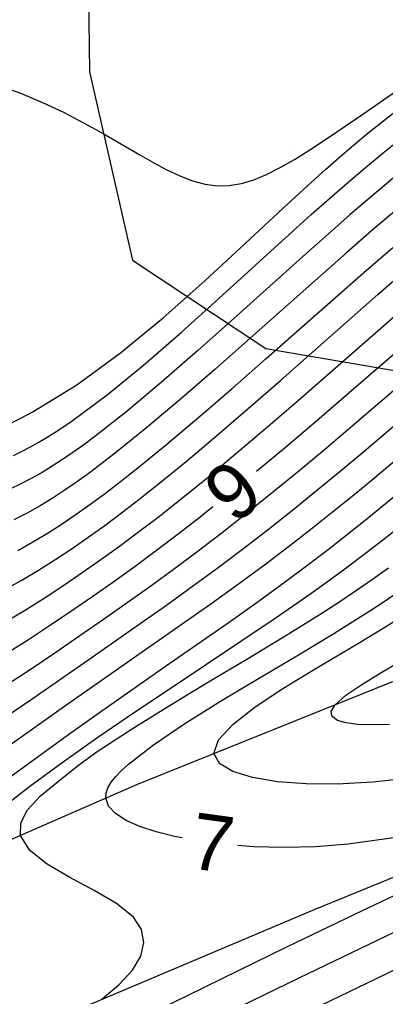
# Model space of a CAD drawing. Extents: x 2602990 to 2605851, y 618069 to 619180.
# Drawn here: x 2603320.28 to 2603333.31, y 618439.82 to 618474.55 of the extents above; entities that cross this region are included whole.
import ezdxf

# ---------------------------------------------------------------- set-up
doc = ezdxf.new("R2010")
doc.units = 0
for name, color, linetype in [('DTM Contours Major', 7, 'Continuous'), ('DTM Contours Minor', 7, 'Continuous'), ('DTM Contours Minor Text', 7, 'Continuous'), ('Exist DTM Crownline', 7, 'Continuous'), ('Exist DTM QL2 LIDAR Elevation Point', 7, 'Continuous'), ('Exist Roads EOP', 7, 'Continuous'), ('PH Exist DTM Breakline', 7, 'Continuous'), ('PH Exist DTM Obscure Area', 7, 'Continuous')]:
    doc.layers.add(name, color=color, linetype=linetype)

msp = doc.modelspace()

# ---------------------------------------------------------------- linework, layer by layer
at = {"layer": 'DTM Contours Major'}
for points in [[(2603319.853, 618472.09), (2603320.346, 618471.915), (2603321.104, 618471.603), (2603321.843, 618471.254), (2603322.561, 618470.88), (2603323.256, 618470.494), (2603324.568, 618469.736), (2603325.056, 618469.458), (2603325.528, 618469.205), (2603325.988, 618468.987), (2603326.438, 618468.813), (2603326.883, 618468.692), (2603327.324, 618468.635), (2603327.749, 618468.646), (2603328.179, 618468.72), (2603328.62, 618468.854), (2603329.078, 618469.044), (2603329.557, 618469.286), (2603330.063, 618469.576), (2603330.65, 618469.942), (2603331.282, 618470.358), (2603332.501, 618471.187), (2603333.853, 618472.117)], [(2603319.765, 618449.745), (2603320.729, 618450.401), (2603322.709, 618451.772), (2603324.576, 618453.074), (2603325.508, 618453.734), (2603326.437, 618454.4), (2603327.357, 618455.074), (2603328.267, 618455.756), (2603329.141, 618456.43), (2603330.003, 618457.112), (2603330.855, 618457.801), (2603331.697, 618458.494), (2603332.532, 618459.19), (2603334.227, 618460.626)]]:
    msp.add_lwpolyline(points, dxfattribs=at)
at = {"layer": 'DTM Contours Minor'}
for points in [[(2603319.929, 618460.176), (2603320.33, 618460.375), (2603320.728, 618460.586), (2603322.319, 618461.562), (2603323.877, 618462.7), (2603325.398, 618463.947), (2603326.874, 618465.255), (2603328.298, 618466.571), (2603329.663, 618467.846), (2603330.669, 618468.768), (2603331.167, 618469.213), (2603331.665, 618469.65), (2603332.167, 618470.08), (2603332.677, 618470.505), (2603333.864, 618471.449), (2603335.103, 618472.367), (2603336.387, 618473.248), (2603337.712, 618474.083), (2603339.073, 618474.862)], [(2603320.064, 618459.053), (2603320.38, 618459.208), (2603320.673, 618459.361), (2603320.965, 618459.524), (2603321.259, 618459.698), (2603321.554, 618459.882), (2603321.853, 618460.077), (2603322.157, 618460.284), (2603323.396, 618461.204), (2603324.696, 618462.264), (2603326.033, 618463.419), (2603327.38, 618464.627), (2603330.009, 618467.023), (2603330.668, 618467.616), (2603331.315, 618468.189), (2603331.954, 618468.745), (2603332.591, 618469.286), (2603333.231, 618469.814), (2603333.879, 618470.333)], [(2603333.578, 618468.906), (2603332.822, 618468.273), (2603332.056, 618467.615), (2603331.276, 618466.932), (2603330.477, 618466.223), (2603327.912, 618463.923), (2603326.613, 618462.768), (2603325.336, 618461.659), (2603324.11, 618460.632), (2603322.959, 618459.724), (2603322.566, 618459.432), (2603322.184, 618459.16), (2603321.811, 618458.906), (2603321.444, 618458.67), (2603321.081, 618458.45), (2603320.719, 618458.246), (2603320.329, 618458.044), (2603319.935, 618457.857)], [(2603333.71, 618467.798), (2603332.825, 618467.043), (2603331.919, 618466.254), (2603330.989, 618465.435), (2603328.488, 618463.217), (2603327.231, 618462.11), (2603325.999, 618461.043), (2603324.815, 618460.044), (2603323.701, 618459.142), (2603323.224, 618458.772), (2603322.763, 618458.426), (2603322.314, 618458.104), (2603321.875, 618457.803), (2603321.441, 618457.523), (2603321.011, 618457.262), (2603320.548, 618457.001), (2603320.08, 618456.76)], [(2603320.216, 618455.678), (2603320.758, 618455.98), (2603321.296, 618456.303), (2603321.796, 618456.623), (2603322.302, 618456.964), (2603322.815, 618457.327), (2603323.34, 618457.713), (2603323.879, 618458.126), (2603324.437, 618458.566), (2603325.523, 618459.451), (2603326.667, 618460.416), (2603327.853, 618461.437), (2603329.063, 618462.493), (2603332.542, 618465.552), (2603333.57, 618466.443)], [(2603319.717, 618454.258), (2603320.341, 618454.605), (2603320.96, 618454.973), (2603321.576, 618455.362), (2603322.15, 618455.742), (2603322.729, 618456.143), (2603323.317, 618456.565), (2603323.916, 618457.011), (2603324.529, 618457.484), (2603325.161, 618457.984), (2603326.208, 618458.84), (2603327.299, 618459.757), (2603328.423, 618460.722), (2603329.568, 618461.719), (2603333.039, 618464.772), (2603334.18, 618465.764)], [(2603319.757, 618453.128), (2603320.459, 618453.544), (2603321.159, 618453.983), (2603321.859, 618454.442), (2603322.514, 618454.886), (2603323.174, 618455.348), (2603323.842, 618455.83), (2603324.521, 618456.334), (2603325.212, 618456.863), (2603325.918, 618457.418), (2603326.932, 618458.238), (2603327.974, 618459.104), (2603329.037, 618460.006), (2603330.116, 618460.935), (2603332.292, 618462.835), (2603334.573, 618464.827)], [(2603328.72, 618458.492), (2603329.681, 618459.292), (2603330.689, 618460.145), (2603332.708, 618461.879), (2603335.832, 618464.577)], [(2603319.784, 618450.871), (2603320.657, 618451.443), (2603321.541, 618452.039), (2603322.433, 618452.651), (2603323.268, 618453.23), (2603324.107, 618453.82), (2603324.949, 618454.422), (2603325.794, 618455.037), (2603326.641, 618455.667), (2603327.489, 618456.314), (2603328.419, 618457.043), (2603329.349, 618457.79), (2603330.277, 618458.552), (2603331.204, 618459.325), (2603332.127, 618460.105), (2603334.01, 618461.715)], [(2603318.73, 618447.914), (2603321.881, 618450.136), (2603324.019, 618451.628), (2603326.076, 618453.061), (2603327.088, 618453.775), (2603328.079, 618454.487), (2603329.045, 618455.199), (2603329.857, 618455.814), (2603330.649, 618456.428), (2603331.422, 618457.043), (2603332.18, 618457.657), (2603332.926, 618458.272), (2603334.435, 618459.538)], [(2603319.684, 618447.443), (2603320.809, 618448.261), (2603321.991, 618449.11), (2603323.205, 618449.97), (2603325.481, 618451.556), (2603327.705, 618453.105), (2603328.771, 618453.862), (2603329.795, 618454.605), (2603330.542, 618455.163), (2603331.263, 618455.714), (2603331.96, 618456.259), (2603332.639, 618456.801), (2603333.303, 618457.34), (2603333.956, 618457.878)], [(2603319.779, 618451.999), (2603320.564, 618452.491), (2603321.353, 618453.006), (2603322.146, 618453.54), (2603322.889, 618454.051), (2603323.637, 618454.577), (2603324.392, 618455.12), (2603325.154, 618455.682), (2603325.926, 618456.264), (2603326.707, 618456.869), (2603327.165, 618457.233)], [(2603319.55, 618446.45), (2603320.642, 618447.297), (2603321.831, 618448.165), (2603323.074, 618449.036), (2603324.379, 618449.926), (2603325.678, 618450.797), (2603328.197, 618452.47), (2603329.382, 618453.268), (2603330.496, 618454.037), (2603331.194, 618454.534), (2603331.858, 618455.019), (2603332.493, 618455.495), (2603333.104, 618455.965), (2603333.695, 618456.43)], [(2603323.212, 618439.722), (2603323.832, 618440.248), (2603324.297, 618440.761), (2603324.593, 618441.258), (2603324.706, 618441.737), (2603324.624, 618442.197), (2603324.333, 618442.634), (2603323.727, 618443.121), (2603322.934, 618443.588), (2603322.074, 618444.05), (2603321.27, 618444.521), (2603320.644, 618445.013), (2603320.317, 618445.543), (2603320.332, 618445.987), (2603320.568, 618446.458), (2603321.03, 618446.956), (2603321.67, 618447.476), (2603322.335, 618448.007), (2603323.082, 618448.557), (2603324.323, 618449.36), (2603325.646, 618450.177), (2603327.01, 618450.999), (2603328.375, 618451.815), (2603329.701, 618452.615), (2603330.947, 618453.389), (2603331.612, 618453.818), (2603332.243, 618454.238), (2603332.842, 618454.65), (2603333.415, 618455.057)], [(2603326.069, 618445.459), (2603325.801, 618445.51), (2603325.143, 618445.676), (2603324.563, 618445.867), (2603324.076, 618446.081), (2603323.7, 618446.32), (2603323.452, 618446.582), (2603323.348, 618446.867), (2603323.361, 618447.047), (2603323.427, 618447.235), (2603323.542, 618447.433), (2603323.705, 618447.639), (2603323.91, 618447.854), (2603324.155, 618448.078), (2603325.046, 618448.771), (2603326.162, 618449.523), (2603327.433, 618450.314), (2603328.788, 618451.123), (2603330.156, 618451.932), (2603331.466, 618452.72), (2603332.055, 618453.085), (2603332.617, 618453.443), (2603333.155, 618453.794), (2603333.672, 618454.142)], [(2603334.163, 618447.582), (2603332.862, 618447.438), (2603331.589, 618447.367), (2603330.487, 618447.375), (2603329.467, 618447.452), (2603328.579, 618447.6), (2603327.872, 618447.816), (2603327.396, 618448.1), (2603327.201, 618448.453), (2603327.362, 618448.943), (2603327.881, 618449.504), (2603328.673, 618450.118), (2603329.657, 618450.766), (2603330.75, 618451.431), (2603332.352, 618452.381), (2603333.288, 618452.948), (2603333.741, 618453.23)], [(2603330.057, 618439.047), (2603332.964, 618440.446), (2603342.988, 618445.323), (2603344.886, 618446.262), (2603346.848, 618447.254), (2603351.987, 618449.892), (2603353.142, 618450.474), (2603354.326, 618451.053), (2603355.539, 618451.621), (2603356.782, 618452.171)], [(2603333.455, 618449.493), (2603332.828, 618449.475), (2603332.329, 618449.492), (2603331.912, 618449.544), (2603331.599, 618449.635), (2603331.413, 618449.77), (2603331.378, 618449.953), (2603331.516, 618450.189), (2603331.901, 618450.525), (2603332.465, 618450.909), (2603333.124, 618451.312), (2603334.402, 618452.066)], [(2603333.775, 618445.482), (2603331.98, 618445.23), (2603330.813, 618445.14), (2603329.69, 618445.112), (2603328.619, 618445.141), (2603328.049, 618445.185)], [(2603324.536, 618439.014), (2603329.819, 618441.594), (2603332.46, 618442.864), (2603334.567, 618443.861)], [(2603324.379, 618437.64), (2603330.235, 618440.478), (2603334.283, 618442.431)]]:
    msp.add_lwpolyline(points, dxfattribs=at)
at = {"layer": 'Exist DTM Crownline'}
msp.add_spline([(2603233.488, 618380.754), (2603285.185, 618400.095), (2603335.457, 618418.629), (2603390.812, 618439.069), (2603440.087, 618457.325), (2603493.996, 618477.231), (2603542.655, 618495.301), (2603600.808, 618516.867), (2603653.659, 618536.362), (2603706.222, 618555.742), (2603764.811, 618577.593), (2603823.52, 618599.847), (2603878.564, 618620.56), (2603937.951, 618643.078), (2603997.369, 618665.789), (2604036.209, 618680.665), (2604055.311, 618688.017)], degree=3, dxfattribs=at)
at = {"layer": 'Exist DTM QL2 LIDAR Elevation Point'}
msp.add_line((2603330, 618470), (2603330, 618470), dxfattribs=at)
at = {"layer": 'Exist Roads EOP'}
for points in [[(2603230.17, 618389.98), (2603282.929, 618409.597), (2603332.773, 618427.868), (2603388.167, 618448.413), (2603437.203, 618466.721), (2603490.778, 618486.527), (2603539.039, 618504.558), (2603597.451, 618526.156), (2603651.053, 618545.972), (2603705.208, 618566.084), (2603762.02, 618587.183), (2603820.334, 618609.162), (2603876.341, 618629.99), (2603934.909, 618652.28), (2603996.409, 618675.568), (2604033.216, 618689.957), (2604052.01, 618697.199)], [(2604034.633, 618668.486), (2603984.89, 618650.123), (2603936.767, 618631.654), (2603888.195, 618613.335), (2603837.766, 618594.258), (2603782.918, 618573.705), (2603731.939, 618554.39), (2603671.126, 618532.171), (2603621.822, 618514.106), (2603561.545, 618491.877), (2603506.421, 618471.293), (2603452.163, 618451.33), (2603398.364, 618431.316), (2603341.431, 618410.355), (2603281.65, 618388.199), (2603223.033, 618366.475), (2603185.717, 618352.612)]]:
    msp.add_spline(points, degree=3, dxfattribs=at)
at = {"layer": 'PH Exist DTM Breakline'}
for points in [[(2603404.24, 618481.758), (2603388.466, 618475.969), (2603379.869, 618472.664), (2603374.144, 618469.11), (2603368.576, 618465.279), (2603359.621, 618461.346), (2603346.569, 618456.764), (2603335.76, 618451.895), (2603324.441, 618447.344), (2603315.881, 618443.606), (2603310.041, 618440.603)], [(2603126.503, 618365.838), (2603154.104, 618376.189), (2603187.527, 618390.366), (2603202.237, 618396.927), (2603224.555, 618403.695), (2603244.777, 618410.718), (2603259.477, 618415.231), (2603282.926, 618423.896), (2603312.189, 618435.069), (2603330.806, 618442.928), (2603342.63, 618447.748), (2603352.942, 618452.331), (2603359.096, 618454.349), (2603369.435, 618457.345)]]:
    msp.add_lwpolyline(points, dxfattribs=at)
at = {"layer": 'PH Exist DTM Obscure Area'}
msp.add_lwpolyline([(2603341.823, 618527.407), (2603339.877, 618522.925), (2603333.253, 618517.641), (2603327.271, 618512.629), (2603321.006, 618505.877), (2603321.245, 618498.268), (2603321.561, 618487.91), (2603322.637, 618482.772), (2603322.771, 618472.689), (2603324.297, 618465.991), (2603329.048, 618462.852), (2603337.29, 618461.438), (2603349.233, 618467.155), (2603351.635, 618471.268), (2603352.118, 618476.398), (2603355.993, 618481.695), (2603359.499, 618486.444)], dxfattribs=at)

# ---------------------------------------------------------------- texts
at = {"layer": 'DTM Contours Minor Text'}
for s, rotation, p in [('6', 218.9974, (2603327.824, 618459.047)), ('7', 352.1292, (2603326.27, 618444.392))]:
    msp.add_text(s, height=2, rotation=rotation, dxfattribs=at).set_placement(p)

doc.saveas('drawing.dxf')
